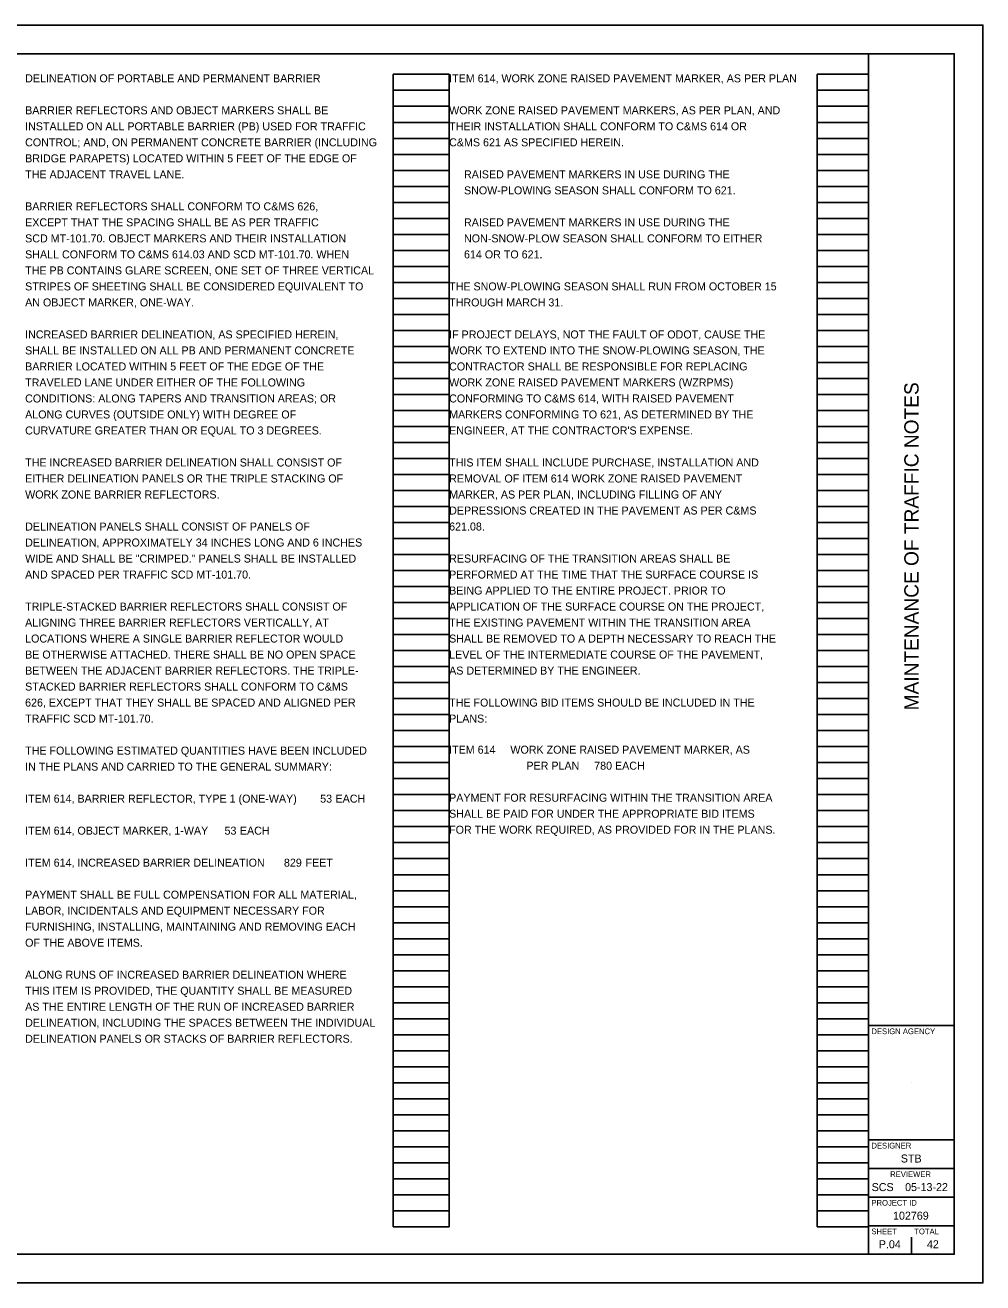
# Model space of a CAD drawing. Extents: x -7.1 to 46.9, y -17.8 to 23.9.
# Drawn here: x 17.24 to 34, y 0 to 22 of the extents above; entities that cross this region are included whole.
import ezdxf

# ---------------------------------------------------------------- set-up
doc = ezdxf.new("R2010")
doc.units = 0
for name, color, linetype in [('SH_Border', 7, 'Continuous'), ('SH_Cut_Line', 7, 'Continuous'), ('SH_Data', 7, 'Continuous'), ('SH_Text', 7, 'Continuous')]:
    doc.layers.add(name, color=color, linetype=linetype)

msp = doc.modelspace()

# ---------------------------------------------------------------- linework, layer by layer
at = {"layer": 'SH_Border'}
for p, q in [((32, 0.5), (32, 21.5)), ((32, 4.5), (33.5, 4.5)), ((32, 2.5), (33.5, 2.5)), ((32, 2), (33.5, 2)), ((32, 1.5), (33.5, 1.5)), ((32, 1), (33.5, 1))]:
    msp.add_line(p, q, dxfattribs=at)
msp.add_lwpolyline([(1.5, 21.5), (33.5, 21.5), (33.5, 0.5), (1.5, 0.5)], close=True, dxfattribs=at)
at = {"layer": 'SH_Cut_Line'}
msp.add_lwpolyline([(0, 0), (34, 0), (34, 22), (0, 22)], close=True, dxfattribs=at)
at = {"layer": 'SH_Data'}
for p, q in [((23.68, 0.98), (23.68, 21.14)), ((23.68, 21.14), (24.66, 21.14)), ((24.66, 0.98), (24.66, 21.14)), ((31.1, 0.98), (31.1, 21.14)), ((31.1, 21.14), (32, 21.14)), ((32, 0.98), (32, 21.14)), ((23.68, 20.86), (24.66, 20.86)), ((31.1, 20.86), (32, 20.86)), ((23.68, 20.58), (24.66, 20.58)), ((31.1, 20.58), (32, 20.58)), ((23.68, 20.3), (24.66, 20.3)), ((31.1, 20.3), (32, 20.3)), ((23.68, 20.02), (24.66, 20.02)), ((31.1, 20.02), (32, 20.02)), ((23.68, 19.74), (24.66, 19.74)), ((31.1, 19.74), (32, 19.74)), ((23.68, 19.46), (24.66, 19.46)), ((31.1, 19.46), (32, 19.46)), ((23.68, 19.18), (24.66, 19.18)), ((31.1, 19.18), (32, 19.18)), ((23.68, 18.9), (24.66, 18.9)), ((31.1, 18.9), (32, 18.9)), ((23.68, 18.62), (24.66, 18.62)), ((31.1, 18.62), (32, 18.62)), ((23.68, 18.34), (24.66, 18.34)), ((31.1, 18.34), (32, 18.34)), ((23.68, 18.06), (24.66, 18.06)), ((31.1, 18.06), (32, 18.06)), ((23.68, 17.78), (24.66, 17.78)), ((31.1, 17.78), (32, 17.78)), ((23.68, 17.5), (24.66, 17.5)), ((31.1, 17.5), (32, 17.5)), ((23.68, 17.22), (24.66, 17.22)), ((31.1, 17.22), (32, 17.22)), ((23.68, 16.94), (24.66, 16.94)), ((31.1, 16.94), (32, 16.94)), ((23.68, 16.66), (24.66, 16.66)), ((31.1, 16.66), (32, 16.66)), ((23.68, 16.38), (24.66, 16.38)), ((31.1, 16.38), (32, 16.38)), ((23.68, 16.1), (24.66, 16.1)), ((31.1, 16.1), (32, 16.1)), ((23.68, 15.82), (24.66, 15.82)), ((31.1, 15.82), (32, 15.82)), ((23.68, 15.54), (24.66, 15.54)), ((31.1, 15.54), (32, 15.54)), ((23.68, 15.26), (24.66, 15.26)), ((31.1, 15.26), (32, 15.26)), ((23.68, 14.98), (24.66, 14.98)), ((31.1, 14.98), (32, 14.98)), ((23.68, 14.7), (24.66, 14.7)), ((31.1, 14.7), (32, 14.7)), ((23.68, 14.42), (24.66, 14.42)), ((31.1, 14.42), (32, 14.42)), ((23.68, 14.14), (24.66, 14.14)), ((31.1, 14.14), (32, 14.14)), ((23.68, 13.86), (24.66, 13.86)), ((31.1, 13.86), (32, 13.86)), ((23.68, 13.58), (24.66, 13.58)), ((31.1, 13.58), (32, 13.58)), ((23.68, 13.3), (24.66, 13.3)), ((31.1, 13.3), (32, 13.3)), ((23.68, 13.02), (24.66, 13.02)), ((31.1, 13.02), (32, 13.02)), ((23.68, 12.74), (24.66, 12.74)), ((31.1, 12.74), (32, 12.74)), ((23.68, 12.46), (24.66, 12.46)), ((31.1, 12.46), (32, 12.46)), ((23.68, 12.18), (24.66, 12.18)), ((31.1, 12.18), (32, 12.18)), ((23.68, 11.9), (24.66, 11.9)), ((31.1, 11.9), (32, 11.9)), ((23.68, 11.62), (24.66, 11.62)), ((31.1, 11.62), (32, 11.62)), ((23.68, 11.34), (24.66, 11.34)), ((31.1, 11.34), (32, 11.34)), ((23.68, 11.06), (24.66, 11.06)), ((31.1, 11.06), (32, 11.06)), ((23.68, 10.78), (24.66, 10.78)), ((31.1, 10.78), (32, 10.78)), ((23.68, 10.5), (24.66, 10.5)), ((31.1, 10.5), (32, 10.5)), ((23.68, 10.22), (24.66, 10.22)), ((31.1, 10.22), (32, 10.22)), ((23.68, 9.94), (24.66, 9.94)), ((31.1, 9.94), (32, 9.94)), ((23.68, 9.66), (24.66, 9.66)), ((31.1, 9.66), (32, 9.66)), ((23.68, 9.38), (24.66, 9.38)), ((31.1, 9.38), (32, 9.38)), ((23.68, 9.1), (24.66, 9.1)), ((31.1, 9.1), (32, 9.1)), ((23.68, 8.82), (24.66, 8.82)), ((31.1, 8.82), (32, 8.82)), ((23.68, 8.54), (24.66, 8.54)), ((31.1, 8.54), (32, 8.54)), ((23.68, 8.26), (24.66, 8.26)), ((31.1, 8.26), (32, 8.26)), ((23.68, 7.98), (24.66, 7.98)), ((31.1, 7.98), (32, 7.98)), ((23.68, 7.7), (24.66, 7.7)), ((31.1, 7.7), (32, 7.7)), ((23.68, 7.42), (24.66, 7.42)), ((31.1, 7.42), (32, 7.42)), ((23.68, 7.14), (24.66, 7.14)), ((31.1, 7.14), (32, 7.14)), ((23.68, 6.86), (24.66, 6.86)), ((31.1, 6.86), (32, 6.86)), ((23.68, 6.58), (24.66, 6.58)), ((31.1, 6.58), (32, 6.58)), ((23.68, 6.3), (24.66, 6.3)), ((31.1, 6.3), (32, 6.3)), ((23.68, 6.02), (24.66, 6.02)), ((31.1, 6.02), (32, 6.02)), ((23.68, 5.74), (24.66, 5.74)), ((31.1, 5.74), (32, 5.74)), ((23.68, 5.46), (24.66, 5.46)), ((31.1, 5.46), (32, 5.46)), ((23.68, 5.18), (24.66, 5.18)), ((31.1, 5.18), (32, 5.18)), ((23.68, 4.9), (24.66, 4.9)), ((31.1, 4.9), (32, 4.9)), ((23.68, 4.62), (24.66, 4.62)), ((31.1, 4.62), (32, 4.62)), ((23.68, 4.34), (24.66, 4.34)), ((31.1, 4.34), (32, 4.34)), ((23.68, 4.06), (24.66, 4.06)), ((31.1, 4.06), (32, 4.06)), ((23.68, 3.78), (24.66, 3.78)), ((31.1, 3.78), (32, 3.78)), ((23.68, 3.5), (24.66, 3.5)), ((31.1, 3.5), (32, 3.5)), ((32.75, 3.5), (32.75, 3.5)), ((23.68, 3.22), (24.66, 3.22)), ((31.1, 3.22), (32, 3.22)), ((23.68, 2.94), (24.66, 2.94)), ((31.1, 2.94), (32, 2.94)), ((23.68, 2.66), (24.66, 2.66)), ((31.1, 2.66), (32, 2.66)), ((23.68, 2.38), (24.66, 2.38)), ((31.1, 2.38), (32, 2.38)), ((23.68, 2.1), (24.66, 2.1)), ((31.1, 2.1), (32, 2.1)), ((23.68, 1.82), (24.66, 1.82)), ((31.1, 1.82), (32, 1.82)), ((23.68, 1.54), (24.66, 1.54)), ((31.1, 1.54), (32, 1.54)), ((23.68, 1.26), (24.66, 1.26)), ((31.1, 1.26), (32, 1.26)), ((23.68, 0.98), (24.66, 0.98)), ((31.1, 0.98), (32, 0.98)), ((32.375, 0.675), (32.375, 0.675)), ((32.75, 0.5), (32.75, 0.8))]:
    msp.add_line(p, q, dxfattribs=at)

# ---------------------------------------------------------------- texts
msp.add_text('MAINTENANCE OF TRAFFIC NOTES', height=0.25, rotation=90, dxfattribs=at).set_placement((32.875, 10.014))
for s, height, p in [('DESIGN AGENCY', 0.1, (32.05, 4.35)), ('DESIGNER', 0.1, (32.05, 2.35)), ('STB', 0.14, (32.565, 2.105)), ('REVIEWER', 0.1, (32.378, 1.85)), ('SCS', 0.14, (32.054, 1.605)), ('05-13-22', 0.14, (32.639, 1.605)), ('PROJECT ID', 0.1, (32.05, 1.35)), ('102769', 0.14, (32.428, 1.105)), ('SHEET', 0.1, (32.05, 0.85)), ('TOTAL', 0.1, (32.8, 0.85)), ('P.04', 0.14, (32.179, 0.605)), ('42', 0.14, (33.021, 0.605))]:
    msp.add_text(s, height=height, dxfattribs=at).set_placement(p)
at = {"layer": 'SH_Text'}
for s, p in [('DELINEATION OF PORTABLE AND PERMANENT BARRIER', (17.24, 21)), ('ITEM 614, WORK ZONE RAISED PAVEMENT MARKER, AS PER PLAN', (24.66, 21)), ('BARRIER REFLECTORS AND OBJECT MARKERS SHALL BE', (17.24, 20.44)), ('WORK ZONE RAISED PAVEMENT MARKERS, AS PER PLAN, AND', (24.66, 20.44)), ('INSTALLED ON ALL PORTABLE BARRIER (PB) USED FOR TRAFFIC', (17.24, 20.16)), ('THEIR INSTALLATION SHALL CONFORM TO C&MS 614 OR', (24.66, 20.16)), ('CONTROL; AND, ON PERMANENT CONCRETE BARRIER (INCLUDING', (17.24, 19.88)), ('C&MS 621 AS SPECIFIED HEREIN.', (24.66, 19.88)), ('BRIDGE PARAPETS) LOCATED WITHIN 5 FEET OF THE EDGE OF', (17.24, 19.6)), ('THE ADJACENT TRAVEL LANE.', (17.24, 19.32)), ('     RAISED PAVEMENT MARKERS IN USE DURING THE', (24.66, 19.32)), ('     SNOW-PLOWING SEASON SHALL CONFORM TO 621.', (24.66, 19.04)), ('BARRIER REFLECTORS SHALL CONFORM TO C&MS 626,', (17.24, 18.76)), ('EXCEPT THAT THE SPACING SHALL BE AS PER TRAFFIC', (17.24, 18.48)), ('     RAISED PAVEMENT MARKERS IN USE DURING THE', (24.66, 18.48)), ('SCD MT-101.70. OBJECT MARKERS AND THEIR INSTALLATION', (17.24, 18.2)), ('     NON-SNOW-PLOW SEASON SHALL CONFORM TO EITHER', (24.66, 18.2)), ('SHALL CONFORM TO C&MS 614.03 AND SCD MT-101.70. WHEN', (17.24, 17.92)), ('     614 OR TO 621.', (24.66, 17.92)), ('THE PB CONTAINS GLARE SCREEN, ONE SET OF THREE VERTICAL', (17.24, 17.64)), ('STRIPES OF SHEETING SHALL BE CONSIDERED EQUIVALENT TO', (17.24, 17.36)), ('THE SNOW-PLOWING SEASON SHALL RUN FROM OCTOBER 15', (24.66, 17.36)), ('AN OBJECT MARKER, ONE-WAY.', (17.24, 17.08)), ('THROUGH MARCH 31.', (24.66, 17.08)), ('INCREASED BARRIER DELINEATION, AS SPECIFIED HEREIN,', (17.24, 16.52)), ('IF PROJECT DELAYS, NOT THE FAULT OF ODOT, CAUSE THE', (24.66, 16.52)), ('SHALL BE INSTALLED ON ALL PB AND PERMANENT CONCRETE', (17.24, 16.24)), ('WORK TO EXTEND INTO THE SNOW-PLOWING SEASON, THE', (24.66, 16.24)), ('BARRIER LOCATED WITHIN 5 FEET OF THE EDGE OF THE', (17.24, 15.96)), ('CONTRACTOR SHALL BE RESPONSIBLE FOR REPLACING', (24.66, 15.96)), ('TRAVELED LANE UNDER EITHER OF THE FOLLOWING', (17.24, 15.68)), ('WORK ZONE RAISED PAVEMENT MARKERS (WZRPMS)', (24.66, 15.68)), ('CONDITIONS: ALONG TAPERS AND TRANSITION AREAS; OR', (17.24, 15.4)), ('CONFORMING TO C&MS 614, WITH RAISED PAVEMENT', (24.66, 15.4)), ('ALONG CURVES (OUTSIDE ONLY) WITH DEGREE OF', (17.24, 15.12)), ('MARKERS CONFORMING TO 621, AS DETERMINED BY THE', (24.66, 15.12)), ('CURVATURE GREATER THAN OR EQUAL TO 3 DEGREES.', (17.24, 14.84)), ("ENGINEER, AT THE CONTRACTOR'S EXPENSE.", (24.66, 14.84)), ('THE INCREASED BARRIER DELINEATION SHALL CONSIST OF', (17.24, 14.28)), ('THIS ITEM SHALL INCLUDE PURCHASE, INSTALLATION AND', (24.66, 14.28)), ('EITHER DELINEATION PANELS OR THE TRIPLE STACKING OF', (17.24, 14)), ('REMOVAL OF ITEM 614 WORK ZONE RAISED PAVEMENT', (24.66, 14)), ('WORK ZONE BARRIER REFLECTORS.', (17.24, 13.72)), ('MARKER, AS PER PLAN, INCLUDING FILLING OF ANY', (24.66, 13.72)), ('DEPRESSIONS CREATED IN THE PAVEMENT AS PER C&MS', (24.66, 13.44)), ('DELINEATION PANELS SHALL CONSIST OF PANELS OF', (17.24, 13.16)), ('621.08.', (24.66, 13.16)), ('DELINEATION, APPROXIMATELY 34 INCHES LONG AND 6 INCHES', (17.24, 12.88)), ('WIDE AND SHALL BE "CRIMPED." PANELS SHALL BE INSTALLED', (17.24, 12.6)), ('RESURFACING OF THE TRANSITION AREAS SHALL BE', (24.66, 12.6)), ('AND SPACED PER TRAFFIC SCD MT-101.70.', (17.24, 12.32)), ('PERFORMED AT THE TIME THAT THE SURFACE COURSE IS', (24.66, 12.32)), ('BEING APPLIED TO THE ENTIRE PROJECT. PRIOR TO', (24.66, 12.04)), ('TRIPLE-STACKED BARRIER REFLECTORS SHALL CONSIST OF', (17.24, 11.76)), ('APPLICATION OF THE SURFACE COURSE ON THE PROJECT,', (24.66, 11.76)), ('ALIGNING THREE BARRIER REFLECTORS VERTICALLY, AT', (17.24, 11.48)), ('THE EXISTING PAVEMENT WITHIN THE TRANSITION AREA', (24.66, 11.48)), ('LOCATIONS WHERE A SINGLE BARRIER REFLECTOR WOULD', (17.24, 11.2)), ('SHALL BE REMOVED TO A DEPTH NECESSARY TO REACH THE', (24.66, 11.2)), ('BE OTHERWISE ATTACHED. THERE SHALL BE NO OPEN SPACE', (17.24, 10.92)), ('LEVEL OF THE INTERMEDIATE COURSE OF THE PAVEMENT,', (24.66, 10.92)), ('BETWEEN THE ADJACENT BARRIER REFLECTORS. THE TRIPLE-', (17.24, 10.64)), ('AS DETERMINED BY THE ENGINEER.', (24.66, 10.64)), ('STACKED BARRIER REFLECTORS SHALL CONFORM TO C&MS', (17.24, 10.36)), ('626, EXCEPT THAT THEY SHALL BE SPACED AND ALIGNED PER', (17.24, 10.08)), ('THE FOLLOWING BID ITEMS SHOULD BE INCLUDED IN THE', (24.66, 10.08)), ('TRAFFIC SCD MT-101.70.', (17.24, 9.8)), ('PLANS:', (24.66, 9.8)), ('THE FOLLOWING ESTIMATED QUANTITIES HAVE BEEN INCLUDED', (17.24, 9.24)), ('ITEM 614     WORK ZONE RAISED PAVEMENT MARKER, AS', (24.66, 9.256)), ('IN THE PLANS AND CARRIED TO THE GENERAL SUMMARY:', (17.24, 8.96)), ('                          PER PLAN     780 EACH', (24.66, 8.976)), ('ITEM 614, BARRIER REFLECTOR, TYPE 1 (ONE-WAY)    ', (17.24, 8.4)), ('53', (22.403, 8.4)), (' EACH', (22.62, 8.4)), ('PAYMENT FOR RESURFACING WITHIN THE TRANSITION AREA', (24.66, 8.416)), ('SHALL BE PAID FOR UNDER THE APPROPRIATE BID ITEMS', (24.66, 8.136)), ('ITEM 614, OBJECT MARKER, 1-WAY   ', (17.24, 7.84)), ('53', (20.729, 7.84)), (' EACH', (20.946, 7.84)), ('FOR THE WORK REQUIRED, AS PROVIDED FOR IN THE PLANS.', (24.66, 7.856)), ('ITEM 614, INCREASED BARRIER DELINEATION   ', (17.24, 7.28)), ('829', (21.769, 7.28)), (' FEET', (22.095, 7.28)), ('PAYMENT SHALL BE FULL COMPENSATION FOR ALL MATERIAL,', (17.24, 6.72)), ('LABOR, INCIDENTALS AND EQUIPMENT NECESSARY FOR', (17.24, 6.44)), ('FURNISHING, INSTALLING, MAINTAINING AND REMOVING EACH', (17.24, 6.16)), ('OF THE ABOVE ITEMS.', (17.24, 5.88)), ('ALONG RUNS OF INCREASED BARRIER DELINEATION WHERE', (17.24, 5.32)), ('THIS ITEM IS PROVIDED, THE QUANTITY SHALL BE MEASURED', (17.24, 5.04)), ('AS THE ENTIRE LENGTH OF THE RUN OF INCREASED BARRIER', (17.24, 4.76)), ('DELINEATION, INCLUDING THE SPACES BETWEEN THE INDIVIDUAL', (17.24, 4.48)), ('DELINEATION PANELS OR STACKS OF BARRIER REFLECTORS.', (17.24, 4.2))]:
    msp.add_text(s, height=0.14, dxfattribs=at).set_placement(p)

doc.saveas('drawing.dxf')
